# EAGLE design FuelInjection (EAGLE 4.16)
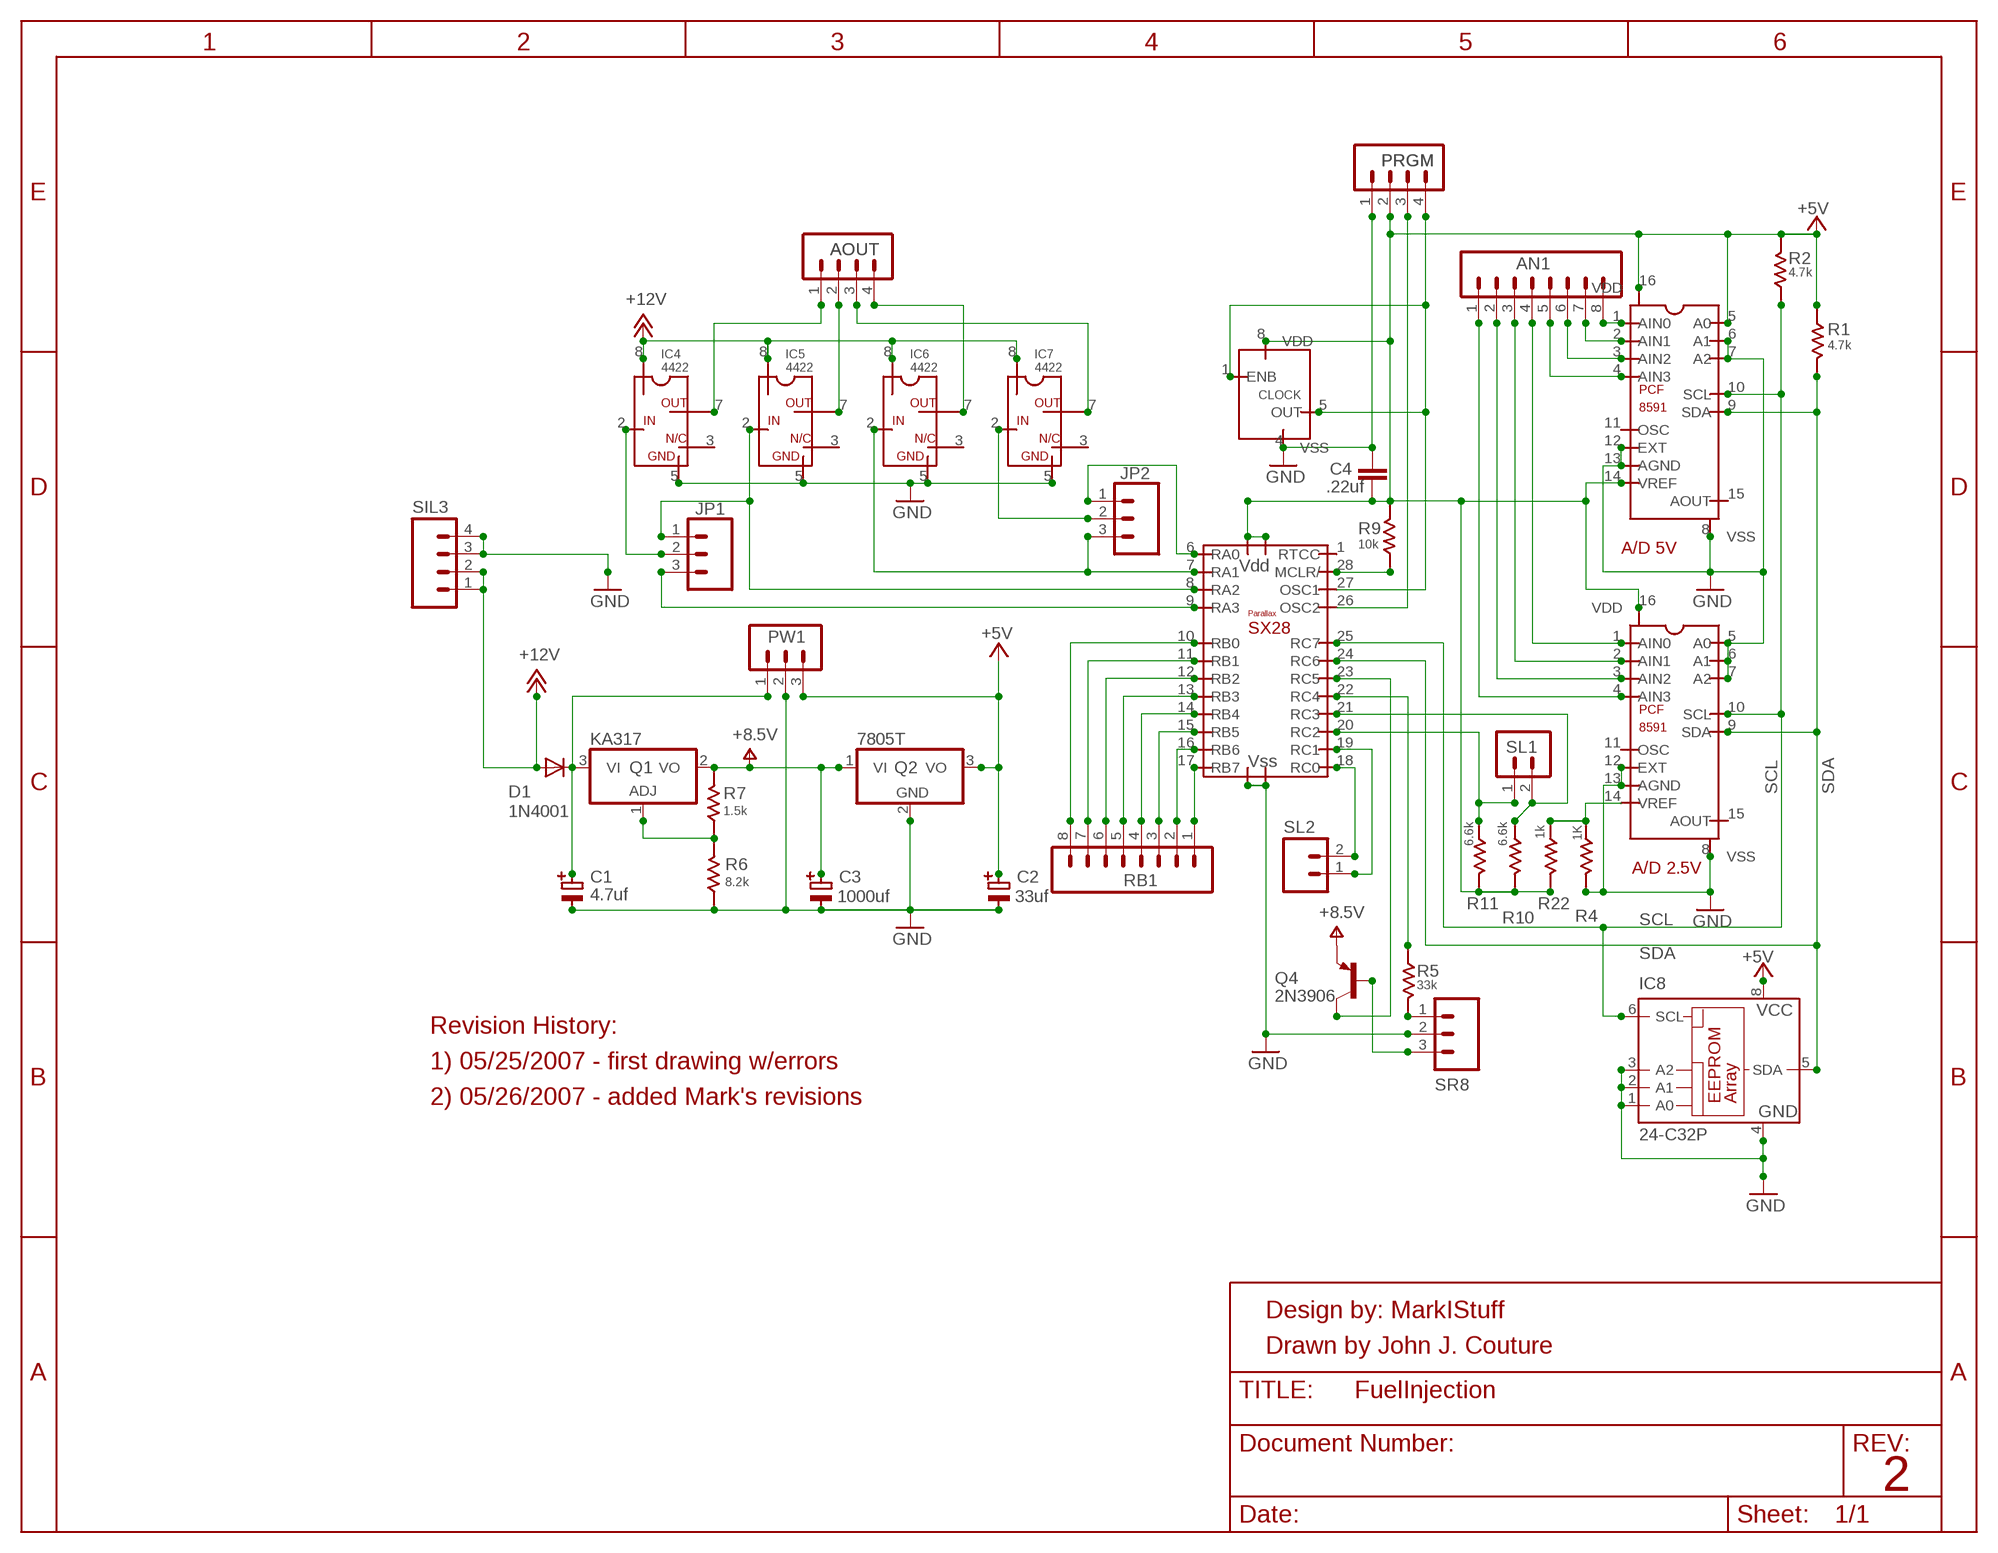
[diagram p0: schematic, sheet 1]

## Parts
AD5  PCF8591  [DIP16]
AD25  PCF8591  [DIP16]
AN1  M08  [08P]
AOUT  M04  [04P]
C1  4.7uf  CAPACITOR  [CAPACITOR]
C2  33uf  CAPACITOR  [CAPACITOR]
C3  1000uf  CAPACITOR  [CAPACITOR]
C4  .22uf  C2.5/5  [C2.5-5]
CLOCK  CLOCK  [DIP8]
D1  1N4001  1N4148  [DO35-10]
IC1  SX28AC/DP  [DIP28]
IC4  4422  [DIP8]
IC5  4422  [DIP8]
IC6  4422  [DIP8]
IC7  4422  [DIP8]
IC8  24-C32P  [DIL8]
JP1  M03  [03P]
JP2  M03  [03P]
PRGM  M04  [04P]
PW1  M03  [03P]
Q1  KA317  317T  [TO220H]
Q2  7805T  [TO220H]
Q4  2N3906  [TO92]
R1  4.7k  RESISTOR  [RESISTOR]
R2  4.7k  RESISTOR  [RESISTOR]
R4  1K  RESISTOR  [RESISTOR]
R5  33k  RESISTOR  [RESISTOR]
R6  8.2k  RESISTOR  [RESISTOR]
R7  1.5k  RESISTOR  [RESISTOR]
R9  10k  RESISTOR  [RESISTOR]
R10  6.6k  RESISTOR  [RESISTOR]
R11  6.6k  RESISTOR  [RESISTOR]
R22  1k  RESISTOR  [RESISTOR]
RB1  M08  [08P]
SIL3  M04  [04P]
SL1  M02  [02P]
SL2  M02  [02P]
SR8  M03  [03P]

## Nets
+5V: AD5.5(A0) AD5.14(VREF) AD5.16(VDD) AD25.16(VDD) C2.+ C4.2 CLOCK.8(VDD) IC1.4(VSS) IC1.5(VSS) IC8.8(VCC) PRGM.2 PW1.3 Q2.3(VO) R1.1 R2.2 R9.2 R10.2 R11.2 R22.2
+12V: D1.A IC4.1(VS$1) IC4.8(VS$8) IC5.1(VS$1) IC5.8(VS$8) IC6.1(VS$1) IC6.8(VS$8) IC7.1(VS$1) IC7.8(VS$8) SIL3.1 SIL3.2
GND: AD5.6(A1) AD5.7(A2) AD5.8(VSS) AD5.12(EXT) AD5.13(AGND) AD25.5(A0) AD25.6(A1) AD25.7(A2) AD25.8(VSS) AD25.12(EXT) AD25.13(AGND) C1.- C2.- C3.- C4.1 CLOCK.4(VSS) IC1.2(VDD) IC1.3(VDD) IC4.4(GND$4) IC4.5(GND$5) IC5.4(GND$4) IC5.5(GND$5) IC6.4(GND$4) IC6.5(GND$5) IC7.4(GND$4) IC7.5(GND$5) IC8.1(A0) IC8.2(A1) IC8.3(A2) IC8.4(GND) PRGM.1 PW1.2 Q2.2(GND) R4.2 R6.1 SIL3.3 SIL3.4 SR8.2
IC5: AOUT.1 IC4.6(OUT$6) IC4.7(OUT$7)
N$1: IC1.7(RA1) IC6.2(IN) JP2.3
N$2: AD5.10(SCL) AD25.10(SCL) IC1.25(RC7) IC8.6(SCL) R2.1
N$4: IC7.2(IN) JP2.2
N$5: IC1.22(RC4) R5.1
N$6: Q4.2(B) SR8.3
N$7: C1.+ D1.C PW1.1 Q1.3(VI)
N$8: IC1.23(RC5) Q4.1(C)
N$9: IC1.28(MCLR/) R9.1
N$10: IC1.14(RB4) RB1.4
N$11: IC1.13(RB3) RB1.5
N$12: IC1.12(RB2) RB1.6
N$13: IC1.11(RB1) RB1.7
N$14: IC1.10(RB0) RB1.8
N$15: IC1.17(RB7) RB1.1
N$16: IC1.16(RB6) RB1.2
N$17: IC1.15(RB5) RB1.3
N$18: AD5.1(AIN0) AN1.8
N$19: AD5.2(AIN1) AN1.7
N$20: AD5.3(AIN2) AN1.6
N$21: AD5.4(AIN3) AN1.5
N$22: AD25.1(AIN0) AN1.4
N$23: AD25.2(AIN1) AN1.3
N$24: AD25.3(AIN2) AN1.2
N$25: AD25.4(AIN3) AN1.1
N$26: IC1.8(RA2) IC5.2(IN) JP1.1
N$27: Q1.1(ADJ) R6.2 R7.1
N$29: IC4.2(IN) JP1.2
N$30: IC1.21(RC3) R10.1 SL1.2
N$31: AOUT.2 IC5.6(OUT$6) IC5.7(OUT$7)
N$32: IC1.9(RA3) JP1.3
N$33: AOUT.3 IC7.6(OUT$6) IC7.7(OUT$7)
N$34: AOUT.4 IC6.6(OUT$6) IC6.7(OUT$7)
N$35: R5.2 SR8.1
N$36: AD5.9(SDA) AD25.9(SDA) IC1.24(RC6) IC8.5(SDA) R1.2
N$40: IC1.20(RC2) R11.1 SL1.1
N$41: IC1.6(RA0) JP2.1
N$43: IC1.26(OSC2) PRGM.3
N$44: IC1.18(RC0) SL2.2
N$45: CLOCK.1(ENB) CLOCK.5(OUT) IC1.27(OSC1) PRGM.4
N$46: IC1.19(RC1) SL2.1
N$47: AD25.14(VREF) R4.1 R22.1
V+: C3.+ Q1.2(VO) Q2.1(VI) Q4.3(E) R7.2 ; supply symbol labelled +8.5V
Unconnected: AD5.11(OSC) AD5.15(AOUT) AD25.11(OSC) AD25.15(AOUT) CLOCK.2(NC$2) CLOCK.3(NC$3) CLOCK.6(NC$6) CLOCK.7(NC$7) IC1.1(RTCC) IC4.3(NC) IC5.3(NC) IC6.3(NC) IC7.3(NC)

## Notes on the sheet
- A/D 5V
- SCL | SDA
- A/D 2.5V
- SCL
- SDA
- Revision History:
- 1) 05/25/2007 - first drawing w/errors
- 2) 05/26/2007 - added Mark's revisions
- Design by: MarkIStuff
- Drawn by John J. Couture
- 2

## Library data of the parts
AD5 AD25 = 0JJC-070505:PCF8591
AN1 RB1 = con-amp-quick:M08: AMP QUICK CONNECTOR
AOUT PRGM SIL3 = con-amp-quick:M04: AMP QUICK CONNECTOR
C1-C3 = 0JJC-070505:CAPACITOR
C4 = capacitor-wima:C: CAPACITOR
CLOCK = 0JJC-070505:CLOCK
D1 = diode:1N4148: DIODE
IC1 = parallax:SX28AC/DP
IC4-IC7 = 0JJC-070505:4422
IC8 = microchip:24-*: Serial EEPROM 32 K/64 K, 1.8 V, I2C
JP1 JP2 PW1 SR8 = con-amp-quick:M03: AMP QUICK CONNECTOR
Q1 = linear:*317: Positive VOLTAGE REGULATOR
Q2 = linear:78*: Positive VOLTAGE REGULATOR Source: http://cache.national.com/ds/LM/LM78L05.pdf http://www.fairchildsemi.com/ds/LM/LM7805.pdf
Q4 = transistor-pnp:2N3906: PNP Transistor
R1 R2 R4-R7 R9-R11 R22 = 0JJC-070505:RESISTOR: 1/4 Watt Resistor
SL1 SL2 = con-amp-quick:M02: AMP QUICK CONNECTOR

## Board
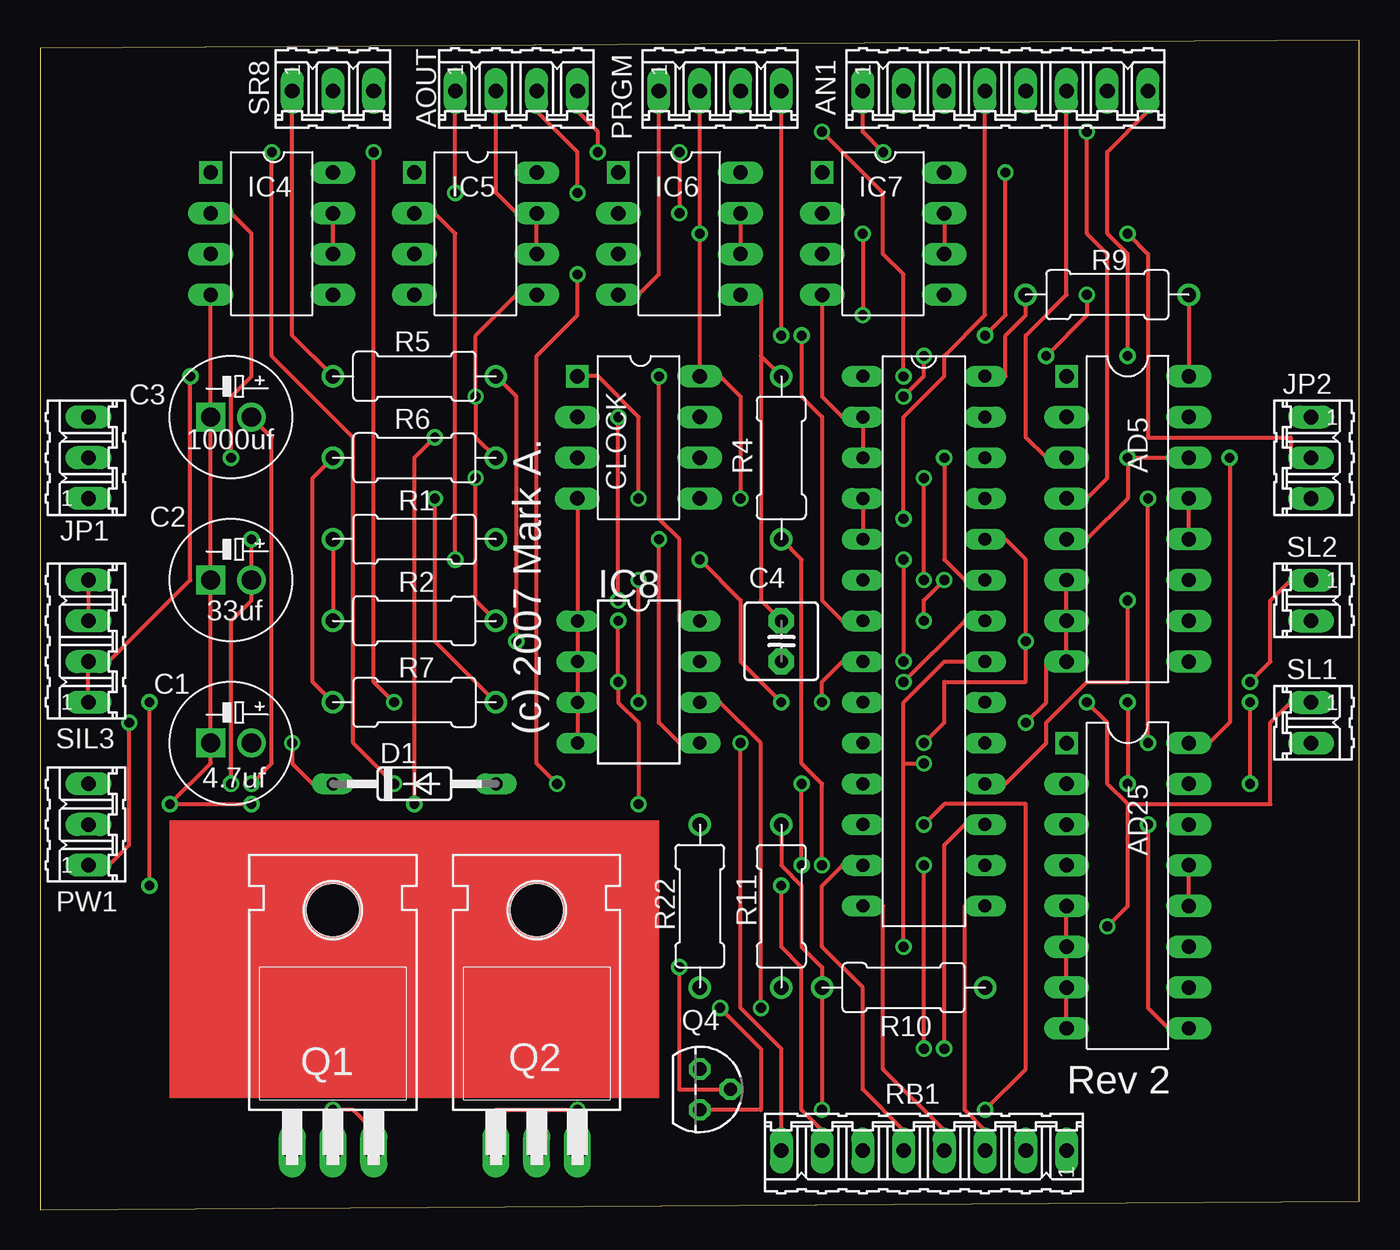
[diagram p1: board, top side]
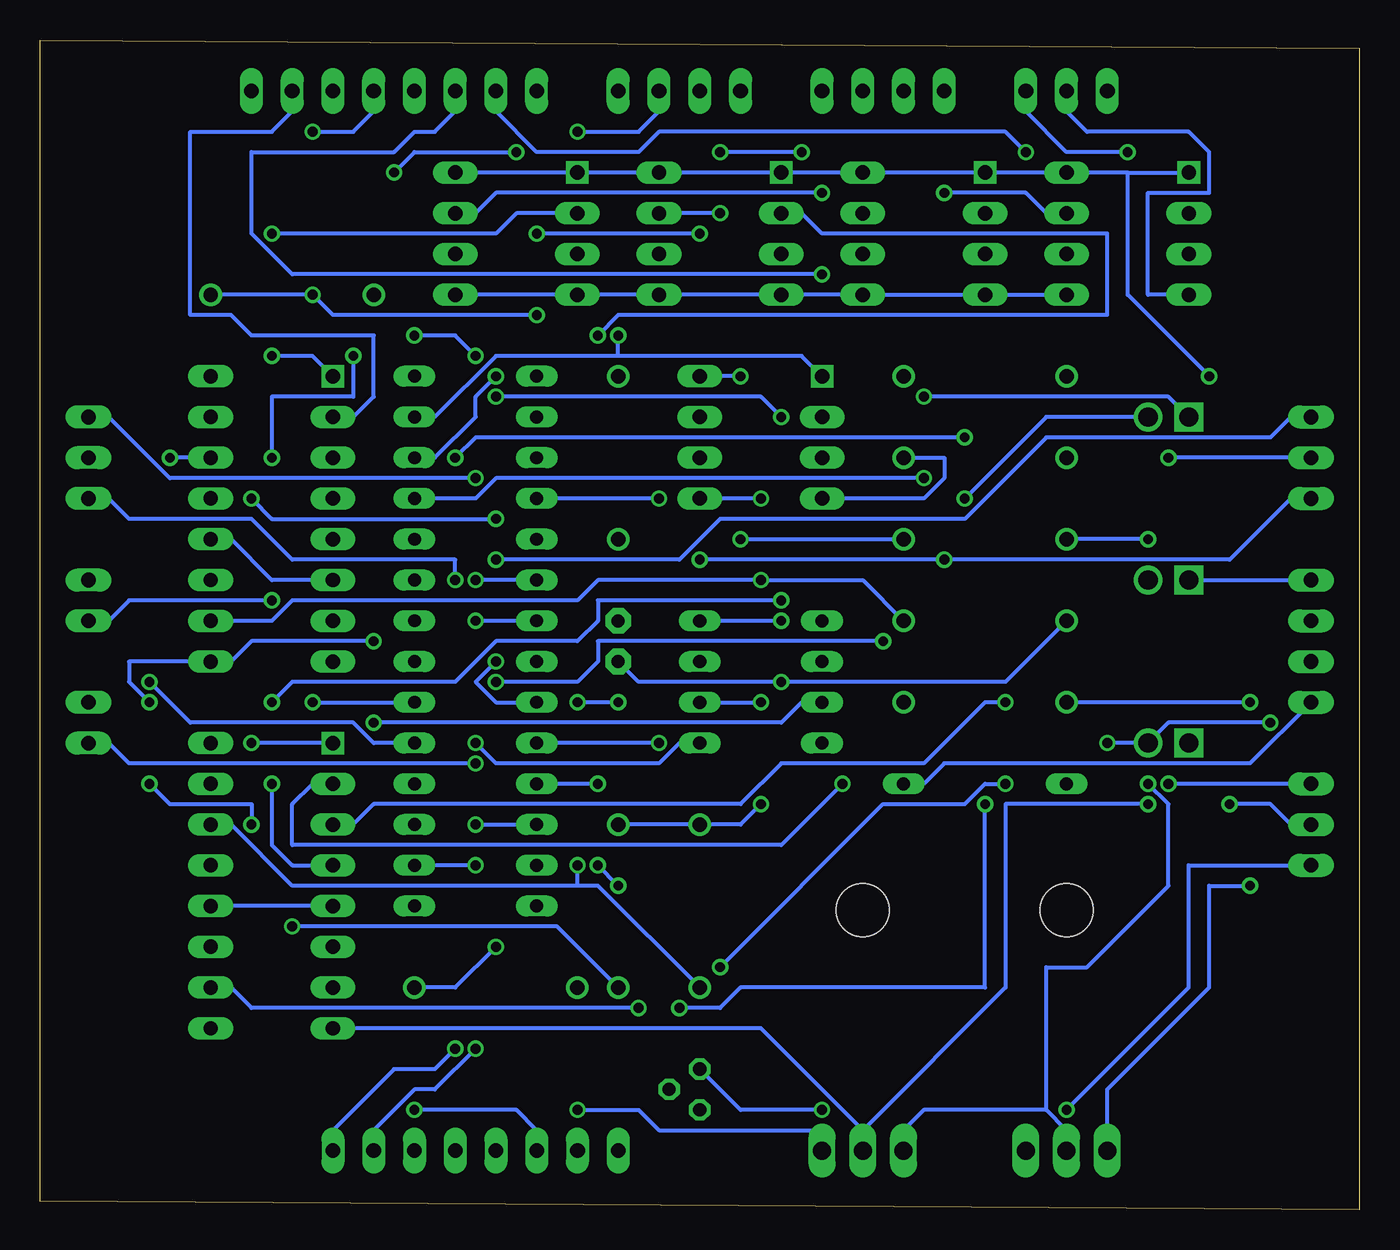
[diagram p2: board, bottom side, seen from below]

Size 82.22 x 72.89 mm. Coordinates in mm from the lower left corner, seen from the top.
Outline: 0,0 82.22,0.51 82.22,72.89 0,72.38 0,0
Copper layers (1*16): Top 0.035mm / dielectric 1.5mm / Bottom 0.035mm
Design rules "default": minimum track width 10mil, minimum drill 24mil, track to track 8mil, track to pad 8mil, pad to pad 8mil, via to via 8mil, smd to smd 8mil, copper to edge 40mil, drill to drill 8mil, minimum pad ring 10mil, minimum via ring 8mil, stop-mask expansion 4mil, vias tented up to drill 0mil, thermal gap 10mil
tRestrict: area 0.5,51.9 to 8.1,72.3; area 74.1,51.9 to 81.8,72.3; area 74.1,1.1 to 81.8,21.5; area 0.5,1.1 to 8.1,18.9
bRestrict: area 0.5,51.9 to 8.1,72.3; area 74.1,51.9 to 81.8,72.3; area 74.1,1.1 to 81.8,21.5; area 0.5,1.1 to 8.1,18.9

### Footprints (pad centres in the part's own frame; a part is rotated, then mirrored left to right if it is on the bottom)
DIP16 = drill 0.9 square: 1 -10.16,-3.81 | drill 0.9 long: 2 -7.62,-3.81; 3 -5.08,-3.81; 4 -2.54,-3.81; 5 0,-3.81; 6 2.54,-3.81; 7 5.08,-3.81; 8 7.62,-3.81; 9 7.62,3.81; 10 5.08,3.81; 11 2.54,3.81; 12 0,3.81; 13 -2.54,3.81; 14 -5.08,3.81; 15 -7.62,3.81; 16 -10.16,3.81
08P = drill 0.914 long: 1 -8.89,0; 2 -6.35,0; 3 -3.81,0; 4 -1.27,0; 5 1.27,0; 6 3.81,0; 7 6.35,0; 8 8.89,0
04P = drill 0.914 long: 1 -3.81,0; 2 -1.27,0; 3 1.27,0; 4 3.81,0
CAPACITOR = drill 1.2 pad 1.778 round: + 1.27,0 | drill 1.2 pad 1.778 square: - -1.27,0
C2.5-5 = drill 0.813 pad 1.6 octagon: 1 -1.27,0; 2 1.27,0
DIP8 = drill 0.9 square: 1 -3.81,5.08 | drill 0.9 long: 2 -3.81,2.54; 3 -3.81,0; 4 -3.81,-2.54; 5 3.81,-2.54; 6 3.81,0; 7 3.81,2.54; 8 3.81,5.08
DO35-10 = drill 0.813 long: A 5.08,0; C -5.08,0
DIP28 = drill 0.8 pad 1.27 long: 1 -2.54,7.62; 2 -2.54,5.08; 3 -2.54,2.54; 4 -2.54,0; 5 -2.54,-2.54; 6 -2.54,-5.08; 7 -2.54,-7.62; 8 -2.54,-10.16; 9 -2.54,-12.7; 10 -2.54,-15.24; 11 -2.54,-17.78; 12 -2.54,-20.32; 13 -2.54,-22.86; 14 -2.54,-25.4; 15 5.08,-25.4; 16 5.08,-22.86; 17 5.08,-20.32; 18 5.08,-17.78; 19 5.08,-15.24; 20 5.08,-12.7; 21 5.08,-10.16; 22 5.08,-7.62; 23 5.08,-5.08; 24 5.08,-2.54; 25 5.08,0; 26 5.08,2.54; 27 5.08,5.08; 28 5.08,7.62
DIL8 = drill 0.813 long: 1 -3.81,-3.81; 2 -1.27,-3.81; 3 1.27,-3.81; 4 3.81,-3.81; 5 3.81,3.81; 6 1.27,3.81; 7 -1.27,3.81; 8 -3.81,3.81
03P = drill 0.914 long: 1 -2.54,0; 2 0,0; 3 2.54,0
TO220H = drill 1.118 long: 1 -2.54,-10.16; 2 0,-10.16; 3 2.54,-10.16 | hole 3.302: 0,4.826
TO92 = drill 0.813 octagon: 1 1.27,0; 2 0,1.905; 3 -1.27,0
RESISTOR = drill 0.9 round: 1 -5.08,0; 2 5.08,0
02P = drill 0.914 long: 1 -1.27,0; 2 1.27,0

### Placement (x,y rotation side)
AD5  67.78,41.78 270 top
AD25  67.78,18.92 270 top
AN1  60.16,69.72 0 top
AOUT  29.68,69.72 0 top
C1  11.9,29.08 0 top
C2  11.9,39.24 0 top
C3  11.9,49.4 0 top
C4  46.19,35.43 270 top
CLOCK  37.3,46.86 0 top
D1  23.33,26.54 0 top
IC1  53.81,44.32 0 top
IC4  14.44,59.56 0 top
IC5  27.14,59.56 0 top
IC6  39.84,59.56 0 top
IC7  52.54,59.56 0 top
IC8  37.3,32.89 270 top
JP1  3.01,46.86 90 top
JP2  79.21,46.86 270 top
PRGM  42.38,69.72 0 top
PW1  3.01,24 90 top
Q1  18.25,13.84 0 top
Q2  30.95,13.84 0 top
Q4  41.11,7.49 270 top
R1  23.33,41.78 0 top
R2  23.33,36.7 180 top
R4  46.19,46.86 90 top
R5  23.33,51.94 180 top
R6  23.33,46.86 180 top
R7  23.33,31.62 0 top
R9  66.51,57.02 0 top
R10  53.81,13.84 180 top
R11  46.19,18.92 90 top
R22  41.11,18.92 90 top
RB1  55.08,3.68 180 top
SIL3  3.01,35.43 90 top
SL1  79.21,30.35 270 top
SL2  79.21,37.97 270 top
SR8  18.25,69.72 0 top

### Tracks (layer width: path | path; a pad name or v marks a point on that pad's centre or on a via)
+5V  (via drill 0.61)
  Top 0.254: v74.13,46.86 74.13,30.35 72.86,29.08 AD25.16 | v62.7,53.21 65.24,55.75 v65.24,57.02 | AD5.5 65.24,41.78 67.78,44.32 v67.78,46.86 AD5.14 | R9.2 AD5.16 | R11.2 46.19,21.46 47.46,20.19 47.46,16.38 48.73,15.11 R10.2 v48.73,6.22 | R1.1 R2.2 | v11.9,26.54 11.9,36.7 13.17,37.97 C2.+ v13.17,41.78 | IC1.4 IC1.5 | PRGM.2 v41.11,60.83 CLOCK.8 42.38,51.94 43.65,50.67 v43.65,44.32 | v38.57,51.94 38.57,43.05 39.84,41.78 39.84,36.7 IC8.8 | v36.03,36.7 v36.03,32.89 36.03,31.62 37.3,30.35 v37.3,25.27 | v51.27,60.83 v51.27,55.75
  Bottom 0.254: AD5.14 v74.13,46.86 | v67.78,46.86 67.78,50.67 62.7,50.67 v62.7,53.21 | R9.2 v65.24,57.02 63.97,55.75 v51.27,55.75 | R11.2 R22.2 38.57,24 v37.3,25.27 | v48.73,6.22 44.92,6.22 43.65,4.95 33.49,4.95 Q2.3 | PW1.3 v11.9,26.54 | v13.17,41.78 R1.1 | v38.57,51.94 CLOCK.8 | C4.2 44.92,32.89 v36.03,32.89 22.06,32.89 R2.2 | v36.03,36.7 IC8.8 | v43.65,44.32 IC1.4 | v41.11,60.83 v51.27,60.83
+12V  (via drill 0.61)
  Top 0.254: SIL3.1 SIL3.2 4.28,34.16 9.36,39.24 v9.36,51.94
  Bottom 0.254: SIL3.1 6.82,27.81 25.87,27.81 27.14,26.54 D1.A | IC7.8 IC7.1 IC6.8 IC6.1 IC5.8 IC5.1 IC4.8 14.44,64.64 | 14.44,64.64 IC4.1 | v9.36,51.94 14.44,57.02 14.44,64.64
GND  (via drill 0.61)
  Top 0.254: IC1.3 IC1.2 50,49.4 48.73,50.67 IC7.4 | 44.92,53.21 R4.2 | 44.92,53.21 44.92,57.02 IC6.5 | C4.1 44.92,37.97 44.92,53.21 | AD5.12 AD5.13 | AD5.6 AD5.7 AD5.8 62.7,34.16 62.7,31.62 v61.43,30.35 | IC8.4 IC8.3 IC8.2 IC8.1 CLOCK.4 | R6.1 27.14,48.13 v27.14,50.67 27.14,54.48 29.68,57.02 IC5.5 | PRGM.1 38.57,58.29 37.3,57.02 IC6.4 | AD25.12 AD25.13 | AD25.5 AD25.6 AD25.7 AD25.8 | SIL3.4 SIL3.3 | IC4.4 C3.- C2.- C1.- 10.63,27.81 v8.09,25.27 v13.17,25.27
  Bottom 0.254: IC7.5 IC7.4 IC6.5 IC6.4 IC5.5 IC5.4 IC4.5 | AD5.12 70.32,41.78 67.78,39.24 AD5.6 | R6.1 25.87,46.86 25.87,45.59 27.14,44.32 CLOCK.4 | v61.43,30.35 36.03,30.35 34.76,31.62 IC8.3 | 30.95,4.95 37.3,11.3 AD25.8 | AD25.5 AD25.12 | v8.09,25.27 5.55,25.27 4.28,24 PW1.2 | C2.- SIL3.4 | SR8.2 18.25,68.45 16.98,67.18 10.63,67.18 9.36,65.91 9.36,63.37 13.17,63.37 13.17,57.02 IC4.4 | 30.95,4.95 22.06,13.84 22.06,25.27 v13.17,25.27 | 30.95,4.95 Q2.2 | v27.14,50.67 11.9,50.67 C3.-
IC5  (via drill 0.61)
  Top 0.254: IC4.6 IC4.7 | v25.87,63.37 AOUT.1
  Bottom 0.254: v25.87,63.37 20.79,63.37 19.52,62.1 IC4.7
N$1  (via drill 0.61)
  Top 0.254: v47.46,54.48 47.46,50.67 48.73,49.4 48.73,37.97 50,36.7 IC1.7 | v56.35,39.24 55.08,37.97 v55.08,36.7
  Bottom 0.254: v47.46,54.48 46.19,55.75 15.71,55.75 15.71,60.83 33.49,60.83 34.76,62.1 IC6.2 | v56.35,39.24 56.35,40.51 66.51,40.51 69.05,43.05 76.67,43.05 77.94,44.32 JP2.3 | IC1.7 v55.08,36.7
N$2  (via drill 0.61)
  Top 0.254: v44.92,12.57 44.92,29.08 42.38,31.62 IC8.6 | v27.14,45.59 27.14,37.97 R2.1 | v37.3,31.62 v37.3,39.24
  Bottom 0.254: v44.92,12.57 69.05,12.57 70.32,13.84 AD25.10 | v27.14,45.59 53.81,45.59 55.08,44.32 IC1.25 | R2.1 30.95,39.24 v37.3,39.24 47.46,39.24 48.73,37.97 66.51,37.97 67.78,36.7 AD5.10 | IC8.6 v37.3,31.62
N$4  (via drill 0.61)
  Top 0.254: v67.78,60.83 69.05,59.56 69.05,48.13 77.94,48.13 77.94,46.86 JP2.2
  Bottom 0.254: v67.78,60.83 53.81,60.83 52.54,62.1 IC7.2
N$5  (via drill 0.61)
  Top 0.254: v53.81,32.89 57.62,36.7 IC1.22 | v29.68,35.43 29.68,50.67 R5.1
  Bottom 0.254: v53.81,32.89 48.73,32.89 47.46,34.16 47.46,35.43 v29.68,35.43
N$6  (via drill 0.61)
  Top 0.254: v39.84,15.11 39.84,7.49 Q4.2 | v22.06,26.54 19.52,29.08 19.52,48.13 14.44,53.21 v14.44,65.91
  Bottom 0.254: v39.84,15.11 29.68,25.27 24.6,25.27 23.33,26.54 v22.06,26.54 | v14.44,65.91 18.25,65.91 20.79,68.45 SR8.3
N$7  (via drill 0.61)
  Top 0.254: v15.71,29.08 15.71,27.81 16.98,26.54 D1.C | v5.55,30.35 5.55,22.73 4.28,21.46 PW1.1 | v18.25,6.22 19.52,6.22 20.79,4.95 Q1.3
  Bottom 0.254: v15.71,29.08 C1.+ 11.9,30.35 v5.55,30.35 | v18.25,6.22 10.63,13.84 10.63,21.46 PW1.1
N$8  (via drill 0.61)
  Top 0.254: v56.35,46.86 56.35,40.51 57.62,39.24 IC1.23 | v24.6,48.13 23.33,46.86 v23.33,25.27 | v42.38,12.57 44.92,10.03 44.92,6.22 Q4.1
  Bottom 0.254: v56.35,46.86 55.08,48.13 v24.6,48.13 | v23.33,25.27 23.33,13.84 38.57,13.84 39.84,12.57 v42.38,12.57
N$9
  Top 0.254: R9.1 61.43,55.75 60.16,54.48 60.16,51.94 IC1.28
N$10
  Top 0.254: IC1.14 52.54,18.92 52.54,8.76 56.35,4.95 RB1.4
N$11
  Top 0.254: IC1.13 50,21.46 48.73,20.19 48.73,16.38 51.27,13.84 51.27,7.49 53.81,4.95 RB1.5
N$12  (via drill 0.61)
  Top 0.254: v55.08,24 56.35,25.27 61.43,25.27 61.43,8.76 v58.89,6.22
  Bottom 0.254: v58.89,6.22 52.54,6.22 51.27,4.95 RB1.6 | v55.08,24 IC1.12
N$13  (via drill 0.61)
  Top 0.254: v47.46,21.46 v47.46,26.54 | v46.19,20.19 46.19,16.38 47.46,15.11 47.46,6.22 48.73,4.95 RB1.7
  Bottom 0.254: v46.19,20.19 v47.46,21.46 | v47.46,26.54 IC1.11
N$14  (via drill 0.61)
  Top 0.254: v43.65,29.08 43.65,12.57 46.19,10.03 RB1.8
  Bottom 0.254: v43.65,29.08 IC1.10
N$15  (via drill 0.61)
  Top 0.254: v56.35,10.03 56.35,22.73 57.62,24 IC1.17
  Bottom 0.254: v56.35,10.03 57.62,8.76 60.16,8.76 63.97,4.95 RB1.1
N$16  (via drill 0.61)
  Top 0.254: v55.08,10.03 v55.08,21.46
  Bottom 0.254: v55.08,10.03 57.62,7.49 58.89,7.49 61.43,4.95 RB1.2 | v55.08,21.46 IC1.16
N$17
  Top 0.254: IC1.15 57.62,18.92 57.62,6.22 58.89,4.95 RB1.3
N$18  (via drill 0.61)
  Top 0.254: v67.78,53.21 67.78,59.56 66.51,60.83 66.51,65.91 69.05,68.45 AN1.8
  Bottom 0.254: AD5.1 65.24,53.21 v67.78,53.21
N$19
  Bottom 0.254: AD5.2 62.7,49.4 61.43,50.67 61.43,54.48 69.05,54.48 70.32,55.75 72.86,55.75 72.86,67.18 67.78,67.18 66.51,68.45 AN1.7
N$20
  Top 0.254: AD5.3 62.7,46.86 61.43,48.13 61.43,54.48 63.97,57.02 AN1.6
N$21  (via drill 0.61)
  Top 0.254: v65.24,67.18 65.24,60.83 66.51,59.56 66.51,45.59 65.24,44.32 AD5.4
  Bottom 0.254: v65.24,67.18 62.7,67.18 61.43,68.45 AN1.5
N$22  (via drill 0.61)
  Top 0.254: v69.05,29.08 v69.05,44.32 | v53.81,43.05 53.81,49.4 56.35,51.94 56.35,53.21 58.89,55.75 AN1.4
  Bottom 0.254: AD25.1 v69.05,29.08 | v69.05,44.32 67.78,43.05 v53.81,43.05
N$23  (via drill 0.61)
  Top 0.254: v32.22,26.54 30.95,27.81 30.95,53.21 33.49,55.75 v33.49,58.29
  Bottom 0.254: v32.22,26.54 36.03,22.73 66.51,22.73 66.51,25.27 65.24,26.54 AD25.2 | v33.49,58.29 66.51,58.29 69.05,60.83 69.05,65.91 60.16,65.91 58.89,67.18 57.62,67.18 56.35,68.45 AN1.3
N$24  (via drill 0.61)
  Top 0.254: v22.06,31.62 20.79,32.89 v20.79,65.91
  Bottom 0.254: v22.06,31.62 23.33,31.62 27.14,27.81 36.03,27.81 38.57,25.27 61.43,25.27 62.7,24 AD25.3 | v20.79,65.91 22.06,67.18 43.65,67.18 44.92,65.91 51.27,65.91 53.81,68.45 AN1.2
N$25  (via drill 0.61)
  Top 0.254: v67.78,31.62 v67.78,26.54 | v36.03,37.97 v36.03,49.4 | v53.81,50.67 55.08,51.94 v55.08,53.21 | v58.89,54.48 60.16,55.75 v60.16,64.64 | v52.54,65.91 51.27,67.18 AN1.1
  Bottom 0.254: v67.78,26.54 67.78,22.73 66.51,21.46 AD25.4 | v67.78,31.62 66.51,32.89 56.35,32.89 53.81,35.43 48.73,35.43 47.46,36.7 47.46,37.97 v36.03,37.97 | v36.03,49.4 37.3,50.67 v53.81,50.67 | v55.08,53.21 56.35,54.48 v58.89,54.48 | v60.16,64.64 58.89,65.91 v52.54,65.91
N$26  (via drill 0.61)
  Top 0.254: v48.73,31.62 48.73,32.89 50,34.16 IC1.8 | v46.19,31.62 43.65,34.16 43.65,37.97 v41.11,40.51 | v25.87,40.51 25.87,60.83 24.6,62.1 IC5.2
  Bottom 0.254: v46.19,31.62 v48.73,31.62 | v41.11,40.51 v25.87,40.51 8.09,40.51 4.28,44.32 JP1.1
N$27  (via drill 0.61)
  Top 0.254: R7.1 16.98,32.89 16.98,45.59 R6.2 | v6.82,20.19 v6.82,31.62
  Bottom 0.254: v6.82,20.19 9.36,20.19 9.36,13.84 15.71,7.49 Q1.1 | v6.82,31.62 R7.1
N$29  (via drill 0.61)
  Top 0.254: v11.9,46.86 11.9,50.67 13.17,51.94 13.17,60.83 11.9,62.1 IC4.2
  Bottom 0.254: JP1.2 v11.9,46.86
N$30  (via drill 0.61)
  Top 0.254: v53.81,16.38 53.81,27.81 | 53.81,27.81 53.81,31.62 56.35,34.16 IC1.21 | 53.81,27.81 v55.08,27.81
  Bottom 0.254: v53.81,16.38 56.35,13.84 R10.1 | v55.08,27.81 76.67,27.81 77.94,29.08 SL1.2
N$31
  Top 0.254: IC5.6 IC5.7 29.68,62.1 28.41,63.37 AOUT.2
N$32  (via drill 0.61)
  Top 0.254: v53.81,40.51 v53.81,34.16
  Bottom 0.254: v53.81,34.16 55.08,32.89 53.81,31.62 IC1.9 | v53.81,40.51 42.38,40.51 39.84,43.05 24.6,43.05 19.52,48.13 5.55,48.13 4.28,49.4 JP1.3
N$33  (via drill 0.61)
  Top 0.254: IC7.7 IC7.6 | v33.49,63.37 33.49,65.91 30.95,68.45 AOUT.3
  Bottom 0.254: v33.49,63.37 53.81,63.37 55.08,62.1 IC7.7
N$34  (via drill 0.61)
  Top 0.254: IC6.7 IC6.6 | v34.76,65.91 34.76,67.18 33.49,68.45 AOUT.4 | v39.84,65.91 v39.84,62.1
  Bottom 0.254: v34.76,65.91 v39.84,65.91 | v39.84,62.1 IC6.7
N$35
  Top 0.254: R5.2 15.71,54.48 SR8.1
N$36  (via drill 0.61)
  Top 0.254: v38.57,41.78 38.57,30.35 39.84,29.08 IC8.5 | IC1.24 60.16,41.78 61.43,40.51 v61.43,35.43 61.43,32.89 56.35,32.89 56.35,30.35 v55.08,29.08 | v69.05,24 69.05,12.57 70.32,11.3 AD25.9 | v75.4,31.62 v75.4,26.54
  Bottom 0.254: v38.57,41.78 R1.2 | v61.43,35.43 69.05,35.43 70.32,34.16 AD5.9 76.67,34.16 76.67,32.89 v75.4,31.62 | v69.05,24 69.05,25.27 74.13,25.27 v75.4,26.54 | v55.08,29.08 53.81,27.81 43.65,27.81 42.38,29.08 IC8.5
N$40  (via drill 0.61)
  Top 0.254: v65.24,31.62 66.51,30.35 66.51,26.54 67.78,25.27 | 67.78,25.27 76.67,25.27 76.67,30.35 77.94,31.62 SL1.1 | v66.51,17.65 67.78,18.92 67.78,25.27
  Bottom 0.254: v65.24,31.62 IC1.20 | R11.1 50,17.65 v66.51,17.65
N$41  (via drill 0.61)
  Top 0.254: v55.08,39.24 v55.08,45.59
  Bottom 0.254: v55.08,45.59 74.13,45.59 77.94,49.4 JP2.1 | IC1.6 v55.08,39.24
N$43  (via drill 0.61)
  Top 0.254: v53.81,51.94 53.81,58.29 52.54,59.56 52.54,63.37 v48.73,67.18
  Bottom 0.254: v53.81,51.94 55.08,50.67 55.08,49.4 57.62,46.86 IC1.26 | v48.73,67.18 44.92,67.18 43.65,68.45 PRGM.3
N$44  (via drill 0.61)
  Top 0.254: v67.78,37.97 67.78,32.89 65.24,32.89 62.7,30.35 62.7,29.08 60.16,26.54 IC1.18
  Bottom 0.254: v67.78,37.97 76.67,37.97 77.94,36.7 SL2.2
N$45  (via drill 0.61)
  Top 0.254: v37.3,44.32 37.3,49.4 34.76,51.94 CLOCK.1 | v46.19,54.48 PRGM.4
  Bottom 0.254: 46.19,53.21 34.76,53.21 CLOCK.1 | 46.19,53.21 53.81,53.21 57.62,49.4 IC1.27 | v37.3,44.32 CLOCK.5 | 46.19,53.21 v46.19,54.48
N$46  (via drill 0.61)
  Top 0.254: v75.4,32.89 76.67,34.16 76.67,37.97 77.94,39.24 SL2.1
  Bottom 0.254: v75.4,32.89 72.86,30.35 62.7,30.35 61.43,29.08 IC1.19
N$47  (via drill 0.61)
  Top 0.254: R4.1 47.46,40.51 47.46,27.81 48.73,26.54 v48.73,21.46
  Bottom 0.254: R22.1 47.46,20.19 48.73,20.19 | 48.73,20.19 66.51,20.19 70.32,24 AD25.14 | 48.73,20.19 v48.73,21.46
V+  (via drill 0.61)
  Top 0.254: v33.49,6.22 28.41,6.22 Q2.1 | R7.2 24.6,35.43 v24.6,44.32 | v13.17,26.54 14.44,27.81 14.44,48.13 C3.+
  Bottom 0.254: Q4.3 38.57,6.22 v33.49,6.22 | 19.52,6.22 18.25,4.95 Q1.2 | 19.52,6.22 27.14,6.22 28.41,4.95 Q2.1 | v24.6,44.32 19.52,49.4 C3.+ | 19.52,6.22 19.52,15.11 16.98,15.11 11.9,20.19 11.9,25.27 v13.17,26.54
(copper drawn outside any net)
  shapes: Top area x1

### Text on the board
tPlace: (c) 2007 Mark A. | Rev 2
